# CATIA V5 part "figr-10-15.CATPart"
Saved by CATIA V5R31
Part number: Part1
Bounding box of the stored display mesh (mm): x -59.023 to 59.085, y -59.069 to 29.542, z 0 to 150
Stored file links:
  D:\PROJECTS\Project 2021\US EDITION\CATIA V5 6R 2021\Resources\Part Files\c10_catia_v5_6r2021_prt\c10_catia_v5_6r2021_prt\figr-10-15.CATPart
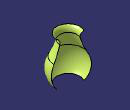
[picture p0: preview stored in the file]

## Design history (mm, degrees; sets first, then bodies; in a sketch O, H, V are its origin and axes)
Set1
  Sketch1 on yz-plane, origin (0, 0, 0), H (0, 1, 0), V (0, 0, 1)
    arc A1 centre (219.5293, 176.8574) radius 194.8379 from (50.3627, 80.1907) to (30.3627, 130.1907) cw
    arc A2 centre (-7.8186, 46.9443) radius 67.0103 from (50.3627, 80.1907) to (40, 0) cw
    arc A3 centre (47.0688, 134.312) radius 17.207 from (30.3627, 130.1907) to (40, 150) cw
    axis line L1 (0, 156.5671) -> (0, -24.1442)
    vertical: L1 V
  Revol1: Element1 Sketch1, Angle1 -60
Body1 (main body)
